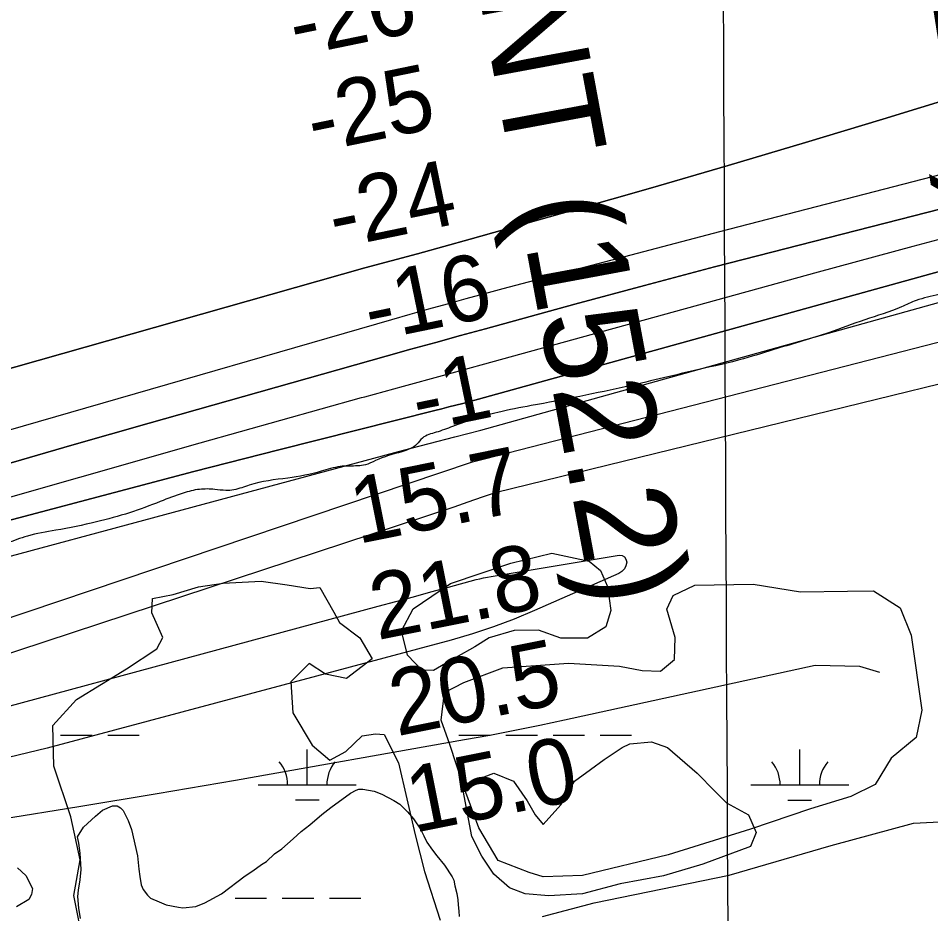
# Model space of a CAD drawing. Extents: x 3445503 to 3483459, y 540493 to 566012.
# Drawn here: x 3459462 to 3460392, y 549125 to 550038 of the extents above; entities that cross this region are included whole.
import ezdxf

# ---------------------------------------------------------------- set-up
doc = ezdxf.new("R2010")
doc.units = 0
for name, color, linetype in [('V-CHAN-NAID', 7, 'Continuous'), ('V-GRID-MAJR', 7, 'Continuous'), ('V-RIVR-EDGE', 7, 'Continuous'), ('V-RIVR-RANG', 7, 'Continuous'), ('V-SITE-VEGE', 7, 'Continuous'), ('V-TOPO-DPTH', 7, 'Continuous'), ('V-TOPO-MINR', 7, 'Continuous'), ('V-TOPO-SHOR', 7, 'Continuous'), ('V-TOPO-WATR', 7, 'Continuous'), ('V-WETL-SWMP', 7, 'Continuous')]:
    doc.layers.add(name, color=color, linetype=linetype)

msp = doc.modelspace()

# ---------------------------------------------------------------- linework, layer by layer
at = {"layer": 'V-GRID-MAJR'}
msp.add_spline([(3460200.663, 545938.965), (3460170.705, 551996.853), (3460140.731, 558057.825), (3460110.758, 564118.814), (3460110.7430000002, 564121.882)], degree=3, dxfattribs=at)
at = {"layer": 'V-RIVR-EDGE'}
msp.add_spline([(3461691.094660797, 550090.6249650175), (3461685.1789394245, 550088.2061703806), (3461682.0528512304, 550089.2567956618), (3461676.1543216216, 550093.7905942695), (3461669.897847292, 550094.1536965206), (3461662.245696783, 550092.4344591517), (3461650.0717819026, 550089.6835074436), (3461638.5888284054, 550085.1926882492), (3461634.052451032, 550078.251269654), (3461621.8613443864, 550068.5477247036), (3461600.981215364, 550059.5609287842), (3461578.709708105, 550050.2299415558), (3461554.0022144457, 550039.8620824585), (3461533.464557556, 550028.788648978), (3461518.844341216, 550020.8292694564), (3461501.789857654, 550012.5282773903), (3461491.349793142, 550008.0348794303), (3461484.3937615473, 550006.6615525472), (3461481.268532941, 550008.0598074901), (3461477.0952578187, 550007.3748632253), (3461469.4396689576, 550004.2651072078), (3461447.1587062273, 549991.1101936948), (3461439.5048365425, 549988.6956970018), (3461429.772065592, 549989.0673951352), (3461421.7757237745, 549988.7395360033), (3461411.688446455, 549986.3310564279), (3461391.512172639, 549980.8188379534), (3461375.1538079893, 549972.8637563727), (3461352.874564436, 549960.4041021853), (3461336.8595315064, 549950.7100127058), (3461318.7724740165, 549946.58315535), (3461308.695511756, 549948.3462317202), (3461291.3260628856, 549953.2560264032), (3461279.5075139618, 549953.6328820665), (3461264.555140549, 549951.9316960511), (3461242.29824629, 549948.5104130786), (3461221.077364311, 549942.3055140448), (3461196.3819048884, 549936.8044702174), (3461168.909706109, 549933.048451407), (3461154.2980856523, 549928.5653685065), (3461121.5968289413, 549918.9125392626), (3461097.9227687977, 549904.7181751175), (3461074.941389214, 549889.4792028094), (3461062.746844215, 549878.3851392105), (3461055.779637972, 549872.4926267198), (3461050.912822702, 549872.5046609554), (3461047.7944708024, 549876.6839531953), (3461040.5080013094, 549882.2640791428), (3461033.9038973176, 549882.6280409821), (3461022.0810504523, 549881.2667483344), (3461014.7808275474, 549881.2847996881), (3461005.4051417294, 549885.4795645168), (3460996.3719280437, 549887.5876917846), (3460985.5945489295, 549887.2667093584), (3460970.6421755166, 549885.5655233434), (3460956.391078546, 549886.2960257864), (3460942.4876112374, 549887.0256686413), (3460929.2759649, 549886.3630736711), (3460917.800747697, 549885.0009214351), (3460903.5470719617, 549884.6885348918), (3460887.1955840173, 549879.5144906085), (3460852.755319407, 549869.5183296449), (3460840.2286173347, 549864.6824595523), (3460821.1029688, 549862.2963292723), (3460795.699356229, 549851.5825596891), (3460790.471157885, 549846.0333789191), (3460788.726132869, 549843.2566395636), (3460784.89962782, 549842.2232060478), (3460781.4336462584, 549846.4033578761), (3460776.9178990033, 549847.805051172), (3460767.1842684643, 549847.8291196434), (3460736.221160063, 549838.1719924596), (3460692.04382656, 549826.8093813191), (3460656.9091622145, 549817.1625691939), (3460631.169094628, 549810.9688448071), (3460623.867152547, 549810.2916368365), (3460614.476853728, 549808.5766974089), (3460594.3048778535, 549804.802627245), (3460589.4286071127, 549800.9907351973), (3460582.117209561, 549796.4896009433), (3460575.150862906, 549790.9447181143), (3460546.6246004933, 549782.6720924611), (3460534.794017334, 549778.1821328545), (3460511.8453021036, 549776.1530877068), (3460498.637953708, 549777.2286410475), (3460487.861434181, 549777.2552882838), (3460473.6034605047, 549775.2047534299), (3460462.1205070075, 549770.7139342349), (3460451.331093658, 549765.5261365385), (3460445.0746193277, 549765.8892387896), (3460436.039686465, 549767.3021067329), (3460430.129122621, 549766.9690900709), (3460422.8237421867, 549764.9013634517), (3460399.859554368, 549756.6149843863), (3460376.5528944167, 549750.4152428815), (3460361.5884867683, 549743.8472415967), (3460324.3594485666, 549730.7292903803), (3460287.4780400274, 549717.6104795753), (3460234.9455603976, 549701.4016832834), (3460200.852065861, 549691.0570330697), (3460155.2850732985, 549680.0454899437), (3460083.2836134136, 549663.18957127), (3459984.5069332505, 549643.2711739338), (3459950.4220345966, 549636.4028203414), (3459904.151186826, 549621.9166997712), (3459887.4503500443, 549616.0482557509), (3459873.530550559, 549610.1729350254), (3459867.9530033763, 549603.9293545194), (3459852.6383873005, 549596.3193238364), (3459825.8485540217, 549587.3471409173), (3459815.4084895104, 549582.8537429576), (3459807.758058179, 549581.8297649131), (3459789.679596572, 549581.1792041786), (3459770.547930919, 549576.3596662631), (3459736.4630322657, 549569.4913126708), (3459697.162829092, 549562.2882232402), (3459681.50746006, 549557.460089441), (3459673.162628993, 549556.7854602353), (3459662.04105857, 549557.855856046), (3459646.397723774, 549557.8945375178), (3459629.702044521, 549554.1118714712), (3459606.389367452, 549545.4787223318), (3459575.0743314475, 549534.0843064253), (3459541.3310453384, 549524.7816856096), (3459499.941625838, 549516.19323506), (3459471.0737508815, 549510.3548766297), (3459449.8502901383, 549503.107088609), (3459421.32660649, 549495.8773519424), (3459395.9324493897, 549488.9875086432), (3459373.321908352, 549483.1336776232), (3459354.8786253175, 549475.5313832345), (3459342.7064296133, 549473.4756908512), (3459324.6210913, 549470.0440928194), (3459296.0956884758, 549462.1190968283), (3459240.4336822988, 549445.5704071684), (3459208.4216677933, 549433.4824511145), (3459176.059444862, 549420.352465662), (3459163.8786532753, 549414.8204766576), (3459142.316158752, 549411.0498448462), (3459129.447844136, 549408.6482419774), (3459115.879972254, 549404.510209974), (3459080.0517677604, 549395.5603763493), (3459049.784778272, 549386.2491596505), (3459013.611522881, 549378.3430746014), (3458998.650553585, 549373.1655919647), (3458977.427092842, 549365.9178039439), (3458951.3359572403, 549358.3344204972), (3458937.746595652, 549345.5056469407), (3458926.970076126, 549345.5322941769), (3458917.2407435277, 549347.2945109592), (3458911.678668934, 549347.3082643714), (3458881.4133986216, 549338.692306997), (3458872.3543972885, 549330.3715444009), (3458862.9615197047, 549327.613715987), (3458852.185000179, 549327.6403632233), (3458812.5165372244, 549312.0950214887), (3458799.2997333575, 549309.3466485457), (3458789.554068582, 549304.5039017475), (3458776.684034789, 549301.4070395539), (3458769.0113588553, 549300.6681868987)], degree=3, dxfattribs=at)
at = {"layer": 'V-SITE-VEGE'}
for points in [[(3459907.595, 549386.466), (3459884.914, 549373.343), (3459873.119, 549373.529), (3459858.194, 549388.936), (3459852.4080000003, 549413.748), (3459863.998, 549436.036), (3459902.045, 549461.839), (3459963.619, 549482.773), (3460005.353, 549492.786), (3460043.431, 549484.879), (3460055.074, 549475.145), (3460062.119, 549458.738), (3460065.666, 549434.525), (3460060.346, 549417.754), (3460041.623, 549406.252), (3460014.653, 549406.1190000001), (3459991.75, 549414.348), (3459967.024, 549414.178), (3459941.625, 549406.715), (3459926.869, 549397.3960000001)], [(3459914, 549256.398), (3459946.186, 549268.473), (3459966.301, 549260.422), (3459980.381, 549240.296), (3459988.428, 549226.206), (3459996.475, 549216.144), (3460014.5810000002, 549236.27), (3460028.661, 549260.422), (3460044.754, 549272.497), (3460058.8340000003, 549282.561), (3460076.94, 549294.638), (3460084.985, 549298.662), (3460107.114, 549300.676), (3460123.207, 549294.638), (3460153.38, 549268.473), (3460171.486, 549250.36), (3460183.555, 549238.283), (3460205.684, 549226.206), (3460213.733, 549208.094), (3460207.6950000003, 549194.005), (3460159.415, 549175.8910000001), (3460119.185, 549163.816), (3460074.927, 549155.763), (3460036.708, 549145.701), (3460002.5100000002, 549143.688), (3459978.37, 549145.701), (3459962.2770000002, 549151.7390000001), (3459946.186, 549165.827), (3459934.115, 549183.942), (3459924.057, 549204.067)]]:
    msp.add_lwpolyline(points, close=True, dxfattribs=at)
for points in [[(3459780.222, 549233.796), (3459800.221, 549248.208), (3459806.082, 549251.216), (3459808.812, 549252.337), (3459812.687, 549252.273), (3459824.2830000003, 549250.151), (3459832.379, 549247.311), (3459844.292, 549240.919), (3459850.432, 549236.948), (3459858.446, 549229.0650000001), (3459864.536, 549221.993), (3459871.733, 549211.411), (3459875.116, 549204.772), (3459878.11, 549198.134), (3459883.802, 549190.292), (3459888.361, 549184.407), (3459895.965, 549174.984), (3459903.909, 549162.841), (3459905.41, 549159.716), (3459906.481, 549153.885), (3459908.683, 549146.099), (3459909.742, 549139.492), (3459910.049, 549134.448), (3459910.719, 549127.849), (3459911.022, 549122.416)], [(3459525.316, 549120.39), (3459523.544, 549130.884), (3459522.571, 549142.914), (3459523.063, 549149.496), (3459524.779, 549159.935), (3459525.721, 549170.386), (3459524.822, 549187.067), (3459523.432, 549197.1680000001), (3459521.986, 549203.781), (3459528.347, 549213.756), (3459540.537, 549224.801), (3459547.61, 549230.894), (3459557.7600000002, 549235.383), (3459562.409, 549235.312), (3459565.866, 549233.319), (3459568.537, 549230.562), (3459573.802, 549220.4), (3459577.142, 549211.045), (3459583.307, 549184.202), (3459584.64, 549170.615), (3459585.687, 549163.232), (3459587.102, 549154.684), (3459588.966, 549150.002), (3459593.524, 549144.116), (3459596.58, 549141.356), (3459605.431, 549137.337), (3459612.364, 549134.515), (3459625.117, 549131.988), (3459629.373, 549131.531), (3459642.572, 549132.873), (3459651.933, 549136.6), (3459668.7430000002, 549145.638), (3459693.065, 549163.857), (3459700.901, 549169.159), (3459709.531, 549175.612), (3459714.619, 549178.631), (3459722.878, 549186.254), (3459730.327, 549191.562), (3459741.73, 549201.8470000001), (3459749.985, 549209.081), (3459759.009, 549215.917), (3459771.193, 549226.575), (3459780.222, 549233.796)], [(3459996.036, 549122.62), (3460048.504, 549136.395), (3460186.031, 549164.553), (3460289.887, 549194.931), (3460373.96, 549217.756), (3460433.559, 549220.7440000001), (3460500.3170000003, 549214.631), (3460609.177, 549206.162), (3460701.0870000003, 549191.783), (3460764.182, 549167.187), (3460838.305, 549129.493), (3460885.923, 549120.873), (3460988.387, 549134.419), (3461083.051, 549152.019), (3461201.804, 549165.307), (3461285.039, 549170.73)]]:
    msp.add_lwpolyline(points, dxfattribs=at)
at = {"layer": 'V-TOPO-DPTH'}
for points in [[(3459211.3750107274, 549345.7206136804), (3459924.706165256, 549586.0581319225), (3459936.937080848, 549589.1169134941), (3460800.63170732, 549811.1962432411), (3461414.147056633, 549976.7730124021), (3461441.4003756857, 549981.9695481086), (3462062.15943334, 550182.0371497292), (3462087.2406898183, 550188.7564375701), (3462112.4426276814, 550194.949281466), (3462137.8255876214, 550200.3524594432), (3463061.3023886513, 550371.9906867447), (3463612.8066830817, 550520.6483682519), (3463627.7085833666, 550525.3226958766), (3463642.7099954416, 550529.6239653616), (3463657.860675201, 550533.3656476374), (3463673.1108667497, 550536.7342717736), (3463688.4822404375, 550539.3814180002), (3463703.914906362, 550541.4451687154), (3463719.439510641, 550542.6338261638), (3463735.025407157, 550543.2390881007)], [(3459437.942290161, 549580.1082650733), (3459516.4122983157, 549603.0253547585), (3459595.007217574, 549625.5210602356), (3459836.503991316, 549693.5907103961), (3459861.7912832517, 549700.6839964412), (3459887.09035069, 549707.734824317), (3459912.4070813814, 549714.7219649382), (3459937.735587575, 549721.6666473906), (3460028.9918147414, 549746.564272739), (3460100.005349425, 549765.7435635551), (3460171.082991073, 549784.6797222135), (3460720.7147386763, 549925.2380494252), (3460738.2330464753, 549929.5292524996), (3460755.798564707, 549933.6084938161), (3460773.434898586, 549937.3697924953), (3460791.1184428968, 549940.9191294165), (3460808.854789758, 549944.208253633), (3460826.614286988, 549947.362589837), (3461361.191577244, 550029.1249720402)], [(3461361.191577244, 550029.1249720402), (3460826.614286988, 549947.362589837), (3460808.854789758, 549944.208253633), (3460791.1184428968, 549940.9191294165), (3460773.434898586, 549937.3697924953), (3460755.798564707, 549933.6084938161), (3460738.2330464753, 549929.5292524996), (3460720.7147386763, 549925.2380494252), (3460171.082991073, 549784.6797222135), (3460100.005349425, 549765.7435635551), (3460028.9918147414, 549746.564272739), (3459937.735587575, 549721.6666473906), (3459912.4070813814, 549714.7219649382), (3459887.09035069, 549707.734824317), (3459861.7912832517, 549700.6839964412), (3459836.503991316, 549693.5907103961), (3459595.007217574, 549625.5210602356), (3459516.4122983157, 549603.0253547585), (3459437.942290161, 549580.1082650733)], [(3460583.808038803, 550009.264407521), (3460342.5307023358, 549935.2139266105), (3460263.8454100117, 549911.3677169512), (3460185.051110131, 549887.892153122), (3460106.093298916, 549864.9725580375), (3460027.026480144, 549842.4236087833), (3459922.237053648, 549812.9378217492), (3459895.466775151, 549805.4698089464), (3459868.674620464, 549798.0818278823), (3459841.849651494, 549790.8138944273), (3459815.0028063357, 549783.625992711), (3459125.9827864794, 549588.2926692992)], [(3459125.9827864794, 549588.2926692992), (3459815.0028063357, 549783.625992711), (3459841.849651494, 549790.8138944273), (3459868.674620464, 549798.0818278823), (3459895.466775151, 549805.4698089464), (3459922.237053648, 549812.9378217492), (3460027.026480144, 549842.4236087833), (3460106.093298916, 549864.9725580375), (3460185.051110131, 549887.892153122), (3460263.8454100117, 549911.3677169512), (3460342.5307023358, 549935.2139266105), (3460583.808038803, 550009.264407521)], [(3459381.3270394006, 549507.347929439), (3459640.5326789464, 549576.041096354), (3459727.1412477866, 549598.1516705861), (3459886.140081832, 549638.2476999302), (3459893.3138416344, 549640.0643955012), (3459900.4851574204, 549641.8906482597), (3459907.6528071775, 549643.7312367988), (3459914.8180129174, 549645.5813825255), (3460665.003131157, 549853.3982233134), (3460734.628720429, 549871.834923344), (3460750.0917222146, 549875.8344571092), (3460765.583799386, 549879.7150161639), (3460781.119489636, 549883.417113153), (3460796.684255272, 549887.0002354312), (3461333.6994842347, 549993.2440759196)], [(3461333.6994842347, 549993.2440759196), (3460796.684255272, 549887.0002354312), (3460781.119489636, 549883.417113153), (3460765.583799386, 549879.7150161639), (3460750.0917222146, 549875.8344571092), (3460734.628720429, 549871.834923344), (3460665.003131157, 549853.3982233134), (3459914.8180129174, 549645.5813825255), (3459907.6528071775, 549643.7312367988), (3459900.4851574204, 549641.8906482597), (3459893.3138416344, 549640.0643955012), (3459886.140081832, 549638.2476999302), (3459727.1412477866, 549598.1516705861), (3459640.5326789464, 549576.041096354), (3459381.3270394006, 549507.347929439)]]:
    msp.add_lwpolyline(points, dxfattribs=at)
at = {"layer": 'V-TOPO-MINR'}
for points in [[(3459211.3750107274, 549345.7206136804), (3459924.706165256, 549586.0581319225), (3459936.937080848, 549589.1169134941), (3460800.63170732, 549811.1962432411), (3461414.147056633, 549976.7730124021), (3461441.4003756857, 549981.9695481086), (3462062.15943334, 550182.0371497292), (3462087.2406898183, 550188.7564375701), (3462112.4426276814, 550194.949281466), (3462137.8255876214, 550200.3524594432), (3463061.3023886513, 550371.9906867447), (3463612.8066830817, 550520.6483682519), (3463627.7085833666, 550525.3226958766), (3463642.7099954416, 550529.6239653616), (3463657.860675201, 550533.3656476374), (3463673.1108667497, 550536.7342717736), (3463688.4822404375, 550539.3814180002), (3463703.914906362, 550541.4451687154), (3463719.439510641, 550542.6338261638), (3463735.025407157, 550543.2390881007)], [(3459155.637951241, 549293.2503730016), (3459905.8141502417, 549540.0580665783), (3459920.2003463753, 549545.1603126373), (3459934.6280149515, 549550.1440796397), (3459949.0833318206, 549555.0488606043), (3460803.9267161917, 549764.415218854), (3461388.204714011, 549956.3590145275), (3461392.7501720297, 549957.209228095), (3461397.292859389, 549958.0744600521), (3462102.286269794, 550164.5635175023), (3462113.6423668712, 550166.9519147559), (3462125.0704581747, 550168.9678788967), (3462136.54654563, 550170.7355542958), (3463026.4969667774, 550338.4731981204), (3463037.8028983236, 550339.9877120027), (3463049.1135204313, 550341.4667887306), (3463060.4272695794, 550342.9222406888), (3463631.137323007, 550468.8590585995), (3463643.2250074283, 550470.516891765), (3463655.385578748, 550471.5073616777), (3463667.5947413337, 550472.0529227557), (3464480.313502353, 550485.9590393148)], [(3459437.942290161, 549580.1082650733), (3459516.4122983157, 549603.0253547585), (3459595.007217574, 549625.5210602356), (3459836.503991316, 549693.5907103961), (3459861.7912832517, 549700.6839964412), (3459887.09035069, 549707.734824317), (3459912.4070813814, 549714.7219649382), (3459937.735587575, 549721.6666473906), (3460028.9918147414, 549746.564272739), (3460100.005349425, 549765.7435635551), (3460171.082991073, 549784.6797222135), (3460720.7147386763, 549925.2380494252), (3460738.2330464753, 549929.5292524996), (3460755.798564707, 549933.6084938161), (3460773.434898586, 549937.3697924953), (3460791.1184428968, 549940.9191294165), (3460808.854789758, 549944.208253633), (3460826.614286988, 549947.362589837), (3461361.191577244, 550029.1249720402)], [(3459187.949324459, 549542.0401291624), (3459842.3286199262, 549731.1375910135), (3459861.225877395, 549736.5450793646), (3459880.1404293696, 549741.8907979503), (3459899.0809231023, 549747.143861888), (3459918.038711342, 549752.3351560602), (3459937.016988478, 549757.451847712), (3459956.005288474, 549762.5308433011), (3460176.675714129, 549820.635832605), (3460738.554335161, 549966.27080303), (3460749.468022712, 549968.2987693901), (3460760.436768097, 549970.0040107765), (3460771.4422187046, 549971.4941021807), (3461211.995207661, 550024.8767643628)], [(3459158.778954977, 549465.899074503), (3459647.023573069, 549605.3710655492), (3459688.114226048, 549617.0380412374), (3459729.2294086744, 549628.6173822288), (3459770.381385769, 549640.0652711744), (3459811.557892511, 549651.4255254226), (3459814.8722694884, 549652.3342377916), (3459854.4063753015, 549663.1875186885), (3459893.935667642, 549674.0582801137), (3459933.457739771, 549684.9552623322), (3460277.2708446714, 549779.7859806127), (3460373.760022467, 549805.9164927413), (3460470.367772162, 549831.6051632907), (3460567.0545697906, 549856.9992727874), (3460702.7443774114, 549892.3055451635), (3460731.696076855, 549899.6096471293), (3460760.715097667, 549906.625976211), (3460789.8351005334, 549913.2106459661), (3460819.022424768, 549919.5075428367), (3461347.41448427, 550011.2692487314)], [(3459125.9827864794, 549588.2926692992), (3459815.0028063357, 549783.625992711), (3459841.849651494, 549790.8138944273), (3459868.674620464, 549798.0818278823), (3459895.466775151, 549805.4698089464), (3459922.237053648, 549812.9378217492), (3460027.026480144, 549842.4236087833), (3460106.093298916, 549864.9725580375), (3460185.051110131, 549887.892153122), (3460263.8454100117, 549911.3677169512), (3460342.5307023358, 549935.2139266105), (3460583.808038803, 550009.264407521)], [(3459181.2506795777, 549416.4231270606), (3459854.14752984, 549597.8819164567), (3459880.4060617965, 549604.7082368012), (3459906.6677706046, 549611.5222957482), (3459932.9342446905, 549618.3179625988), (3460733.057497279, 549841.3578966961), (3460740.821490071, 549843.5815712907), (3460745.7796494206, 549844.988377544), (3460750.7423514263, 549846.3788146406), (3460755.7118674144, 549847.7446980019), (3460760.6859260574, 549849.0942122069), (3460767.5109905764, 549850.9278212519), (3460769.077509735, 549851.3420239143), (3460773.791863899, 549852.5264987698), (3461385.5704638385, 549986.8811627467)], [(3459253.743952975, 549283.1759528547), (3459828.5532564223, 549438.8196270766), (3459846.445012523, 549443.6668141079), (3459864.335907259, 549448.5171766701), (3459882.225509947, 549453.3723025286), (3459900.11425127, 549458.2306039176), (3459928.4433759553, 549465.9283992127), (3459932.1793559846, 549466.8831767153), (3459935.931897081, 549467.762104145), (3459939.709279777, 549468.5272564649), (3459943.5032235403, 549469.2165587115), (3460073.8758728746, 549490.8732656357), (3460077.014171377, 549490.4362334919), (3460079.479924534, 549489.2469365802), (3460080.9368596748, 549486.929242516), (3460081.72124947, 549483.8592836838), (3460080.8545091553, 549480.109090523), (3460079.3212231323, 549476.8190977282), (3460076.788118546, 549474.219405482), (3460073.5884682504, 549472.0799136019), (3459987.858915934, 549434.3003469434), (3459966.9860271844, 549425.6637239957), (3459945.8854694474, 549417.6721385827), (3459924.44340823, 549410.6481094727), (3459902.7736780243, 549404.269117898), (3459491.097634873, 549293.9777123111), (3459431.60758526, 549279.747556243)], [(3460339.604563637, 549371.1592650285), (3460319.246595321, 549377.2565059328), (3460273.5978129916, 549378.3717738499), (3460018.4893854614, 549322.5943506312), (3459993.0855017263, 549317.2022562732), (3459967.6406884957, 549312.0174880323), (3459942.134481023, 549307.1437089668), (3459916.587344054, 549302.4772560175), (3459682.9762473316, 549261.2776392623), (3459603.3031918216, 549247.5456648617), (3459523.562709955, 549234.227277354), (3459443.7210885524, 549221.5292701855)]]:
    msp.add_lwpolyline(points, dxfattribs=at)
at = {"layer": 'V-TOPO-SHOR'}
msp.add_lwpolyline([(3459461.007, 549172.184), (3459469.311, 549164.4670000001), (3459476.403, 549151.151), (3459475.183, 549144.993), (3459472.572, 549139.697), (3459460.093, 549132.309)], dxfattribs=at)
at = {"layer": 'V-TOPO-WATR'}
msp.add_lwpolyline([(3459381.3270394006, 549507.347929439), (3459640.5326789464, 549576.041096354), (3459727.1412477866, 549598.1516705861), (3459886.140081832, 549638.2476999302), (3459893.3138416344, 549640.0643955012), (3459900.4851574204, 549641.8906482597), (3459907.6528071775, 549643.7312367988), (3459914.8180129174, 549645.5813825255), (3460665.003131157, 549853.3982233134), (3460734.628720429, 549871.834923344), (3460750.0917222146, 549875.8344571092), (3460765.583799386, 549879.7150161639), (3460781.119489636, 549883.417113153), (3460796.684255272, 549887.0002354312), (3461333.6994842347, 549993.2440759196)], dxfattribs=at)
at = {"layer": 'V-WETL-SWMP'}
for p, q in [((3459504.9099515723, 549307.4568551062), (3459536.909926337, 549307.4568551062)), ((3459552.909913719, 549307.4568551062), (3459584.9098884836, 549307.4568551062)), ((3459910.7233758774, 549307.3764510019), (3459942.723375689, 549307.3764510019)), ((3459958.7233755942, 549307.3764510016), (3459990.7233754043, 549307.3764510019)), ((3460006.72337531, 549307.3764510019), (3460038.723375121, 549307.3764510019)), ((3460054.7233750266, 549307.3764510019), (3460086.7233748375, 549307.3764510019)), ((3459756.226172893, 549256.7159546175), (3459756.2258752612, 549292.7151745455)), ((3460258.0393451, 549256.6351389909), (3460258.0393654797, 549292.6346508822)), ((3459706.226212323, 549256.7159546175), (3459806.226133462, 549256.7159546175)), ((3460208.0393453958, 549256.6351389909), (3460308.039344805, 549256.6351389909)), ((3459744.226309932, 549241.2852889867), (3459768.226291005, 549241.285288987)), ((3460246.0393364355, 549241.2043482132), (3460270.0393362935, 549241.2043482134)), ((3459682.8191851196, 549141.2864558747), (3459714.819159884, 549141.2864558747)), ((3459730.819147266, 549141.2864558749), (3459762.8191220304, 549141.2864558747)), ((3459778.819109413, 549141.2864558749), (3459810.8190841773, 549141.2864558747))]:
    msp.add_line(p, q, dxfattribs=at)
msp.add_lwpolyline([(3459528.382, 549094.229), (3459518.494, 549143.826), (3459524.6890000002, 549180.247), (3459515.273, 549224.218), (3459498.11, 549275.616), (3459497.0840000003, 549317.208), (3459521.102, 549343.795), (3459572.161, 549375.009), (3459602.821, 549395.311), (3459609.186, 549407.008), (3459602.125, 549422.289), (3459597.7830000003, 549431.909), (3459598.576, 549446.504), (3459619.492, 549450.681), (3459645.255, 549458.443), (3459670.392, 549462.2710000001), (3459709.309, 549464.4720000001), (3459735.734, 549460.672), (3459759.342, 549456.916), (3459768.937, 549457.8910000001), (3459783.201, 549432.903), (3459789.21, 549422.133), (3459809.752, 549406.638), (3459822.332, 549385.089), (3459796.174, 549365.278), (3459774.893, 549369.5480000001), (3459758.211, 549380.487), (3459739.373, 549361.684), (3459741.683, 549330.185), (3459761.387, 549297.287), (3459779.1210000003, 549281.837), (3459795.552, 549290.5650000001), (3459812.099, 549306.596), (3459825.615, 549308.629), (3459834.593, 549307.925), (3459849.304, 549279.039), (3459866.1210000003, 549205.735), (3459875.643, 549168.504), (3459891.71, 549118.808)], dxfattribs=at)
msp.add_lwpolyline([(3459996.756, 549163.133), (3459982.4390000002, 549167.292), (3459950.61, 549179.595), (3459930.915, 549213.055), (3459915.294, 549255.439), (3459901.358, 549297.797), (3459892.7630000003, 549322.653), (3459896.0160000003, 549350.693), (3459915.844, 549361.053), (3459955.411, 549376.157), (3460022.341, 549380.714), (3460074.541, 549377.64), (3460097.508, 549373.343), (3460116.035, 549372.487), (3460130.273, 549384.622), (3460131.19, 549407.08), (3460122.6580000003, 549435.868), (3460129.059, 549449.812), (3460151.133, 549460.137), (3460210.707, 549461.4400000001), (3460258.896, 549453.373), (3460306.666, 549454.301), (3460333.074, 549454.444), (3460360.329, 549437.157), (3460371.688, 549409.448), (3460382.273, 549332.872), (3460376.772, 549304.868), (3460351.1580000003, 549283.925), (3460335.004, 549257.214), (3460310.085, 549244.687), (3460268.878, 549232.4180000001), (3460207.869, 549211.474), (3460124.079, 549185.273), (3460036.662, 549164.186)], close=True, dxfattribs=at)
for centre, radius, start, end in [((3459700.9832764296, 549257.1907475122), 35.24628790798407, 359.22819613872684, 40.77185447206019), ((3459811.469061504, 549257.1907475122), 35.24628790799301, 139.22816090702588, 180.7718192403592), ((3460202.7964095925, 549257.1099357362), 35.24628790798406, 359.2281903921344, 40.77184872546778), ((3460313.282281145, 549257.1099357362), 35.246287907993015, 139.22816647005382, 180.77182480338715)]:
    msp.add_arc(centre, radius, start, end, dxfattribs=at)

# ---------------------------------------------------------------- texts
at = {"layer": 'V-CHAN-NAID'}
for s, rotation, p in [('LWR BELMONT RANGE UPR SIDE FRONT (152.2)', 280.53449283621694, (3459477.2511466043, 552502.9467602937)), ('LWR BELMONT RANGE FRONT (152.2)', 278.8729088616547, (3460048.098091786, 552263.4570882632))]:
    msp.add_text(s, height=100.000002, rotation=rotation, dxfattribs=at).set_placement(p)
at = {"layer": 'V-RIVR-RANG'}
for s, height, rotation, p in [('-26', 67.00000000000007, 11.648055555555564, (3459744.6783098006, 549999.0664957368)), ('-25', 67.00000000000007, 11.648055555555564, (3459763.0762258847, 549900.7569540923)), ('-24', 67.00000000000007, 11.648055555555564, (3459784.83265712, 549803.1387526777)), ('-16', 67.00000000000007, 11.648055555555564, (3459821.05553824, 549708.5039399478)), ('-1', 67.00000000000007, 11.648055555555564, (3459869.6800906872, 549616.4254603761)), ('15.7', 67, 11.368325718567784, (3459807.714452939, 549502.1415074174)), ('21.8', 67, 11.368325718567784, (3459827.662452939, 549404.1505074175)), ('20.5', 67, 11.368325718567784, (3459847.609452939, 549306.1605074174)), ('15.0', 67, 11.368325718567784, (3459864.712806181, 549207.5985623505))]:
    msp.add_text(s, height=height, rotation=rotation, dxfattribs=at).set_placement(p)

doc.saveas('drawing.dxf')
